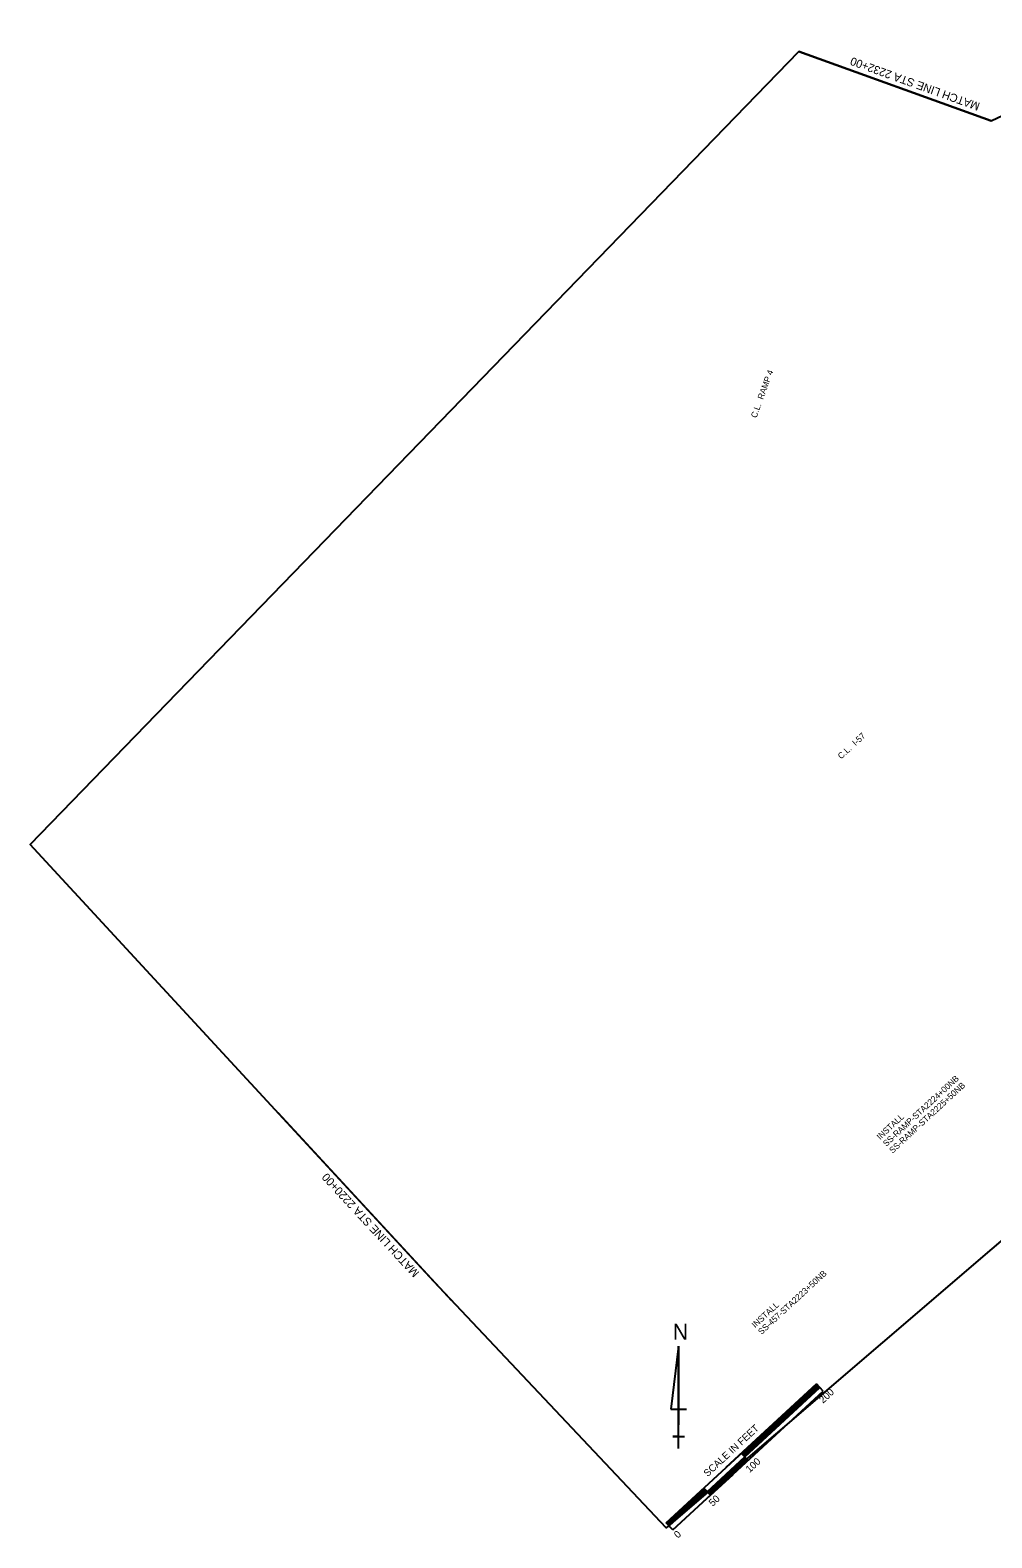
# Model space of a CAD drawing. Extents: x 1726566 to 1728341, y 770862 to 772589.
# Drawn here: x 1726566 to 1727507, y 770862 to 772336 of the extents above; entities that cross this region are included whole.
import ezdxf

# ---------------------------------------------------------------- set-up
doc = ezdxf.new("R2010")
doc.units = 0
for name, color, linetype in [('1', 7, 'Continuous'), ('63', 7, 'Continuous'), ('Level 10', 7, 'Continuous'), ('Plan Notes', 7, 'Continuous'), ('R_Annotation', 7, 'Continuous'), ('R_Draft', 7, 'Continuous')]:
    doc.layers.add(name, color=color, linetype=linetype)

msp = doc.modelspace()

# ---------------------------------------------------------------- linework, layer by layer
at = {"layer": '1'}
msp.add_lwpolyline([(1727876.9, 771723.6), (1727929.7, 771507.1), (1727188.3, 770871.8), (1726961.2, 771112.6), (1726825.5, 771259.4), (1726566.4, 771539.7), (1727317.9, 772315.1), (1727506, 772247.2), (1727694, 772335.9), (1727926.9, 772277.6), (1728062.7, 772130.8), (1727899.7, 771899.8), (1727952.6, 771745.2)], close=True, dxfattribs=at)
at = {"layer": '63'}
for p, q in [((1727200.4, 771049.5), (1727192.7, 770988)), ((1727200.4, 770949.5), (1727200.4, 771049.5)), ((1727200.4, 771049.5), (1727200.4, 770972.6)), ((1727192.7, 770988), (1727208.1, 770988)), ((1727200.4, 770949.5), (1727200.4, 770972.6)), ((1727200.4, 770961.1), (1727194.6, 770961.1)), ((1727194.6, 770961.1), (1727206.1, 770961.1)), ((1727200.4, 770949.5), (1727200.4, 770961.1))]:
    msp.add_line(p, q, dxfattribs=at)
at = {"layer": 'Level 10'}
for p, q in [((1727247, 770931.1), (1727335.2, 771012.6)), ((1727262.3, 770944.1), (1727335.7, 771012)), ((1727262.8, 770943.5), (1727336.2, 771011.4)), ((1727341.7, 771005.5), (1727335.2, 771012.6)), ((1727194.8, 770869.8), (1727341.7, 771005.5)), ((1727263.4, 770942.9), (1727336.8, 771010.8)), ((1727263.9, 770942.3), (1727337.3, 771010.2)), ((1727264.4, 770941.8), (1727337.9, 771009.6)), ((1727265, 770941.2), (1727338.4, 771009)), ((1727188.3, 770876.8), (1727305.8, 770985.4)), ((1727265, 770941.2), (1727309, 770981.9)), ((1727228.3, 770907.2), (1727265, 770941.2)), ((1727228.8, 770906.6), (1727265.5, 770940.6)), ((1727229.4, 770906.1), (1727266.1, 770940)), ((1727229.9, 770905.5), (1727266.6, 770939.4)), ((1727230.4, 770904.9), (1727267.2, 770938.8)), ((1727231, 770904.3), (1727267.7, 770938.2)), ((1727268.3, 770937.6), (1727261.7, 770944.7)), ((1727224.2, 770896.9), (1727253.6, 770924.1)), ((1727188.8, 770876.2), (1727225.6, 770910.2)), ((1727189.4, 770875.6), (1727226.1, 770909.6)), ((1727189.9, 770875), (1727226.6, 770909)), ((1727190.5, 770874.5), (1727227.2, 770908.4)), ((1727231.5, 770903.7), (1727225, 770910.8)), ((1727188.3, 770876.8), (1727217.7, 770904)), ((1727191, 770873.9), (1727227.7, 770907.8)), ((1727194.8, 770869.8), (1727188.3, 770876.8))]:
    msp.add_line(p, q, dxfattribs=at)
at = {"layer": 'Plan Notes'}
for p, q in [((1727506, 772247.2), (1727317.9, 772315.1)), ((1726808.5, 771277.8), (1726978.2, 771094.2))]:
    msp.add_line(p, q, dxfattribs=at)

# ---------------------------------------------------------------- texts
at = {"layer": '63'}
msp.add_text('N', height=15.4, rotation=360, dxfattribs=at).set_placement((1727194.7, 771055.9))
at = {"layer": 'Level 10'}
for s, height, p in [('200', 7, (1727341.6, 770993.1)), ('SCALE IN FEET', 7.001, (1727228.7, 770921.3)), ('100', 7, (1727269.8, 770925.3)), ('50', 7, (1727233.7, 770892.4)), ('0', 7, (1727199.7, 770861.2))]:
    msp.add_text(s, height=height, rotation=42.7503, dxfattribs=at).set_placement(p)
at = {"layer": 'Plan Notes'}
for s, rotation, p in [('MATCH LINE STA 2232+00', 160.1667, (1727495.6, 772264.5)), ('MATCH LINE STA 2220+00', 132.75, (1726947.3, 771121.4))]:
    msp.add_text(s, height=8, rotation=rotation, dxfattribs=at).set_placement(p)
at = {"layer": 'R_Annotation'}
for s, p in [('SS-RAMP-STA2224+00NB', (1727403.5, 771244.2)), ('SS-RAMP-STA2225+50NB', (1727409.6, 771237.5)), ('INSTALL', (1727397.4, 771250.8)), ('SS-457-STA2223+50NB', (1727281.4, 771060.3)), ('INSTALL', (1727275.2, 771066.9))]:
    msp.add_text(s, height=6, rotation=42.75, dxfattribs=at).set_placement(p)
at = {"layer": 'R_Draft'}
for s, rotation, p in [('C.L.  RAMP 4', 69.9952, (1727276.4, 771956.3)), ('C.L.  I-57', 42.6023, (1727359.3, 771622.9))]:
    msp.add_text(s, height=6, rotation=rotation, dxfattribs=at).set_placement(p)

doc.saveas('drawing.dxf')
